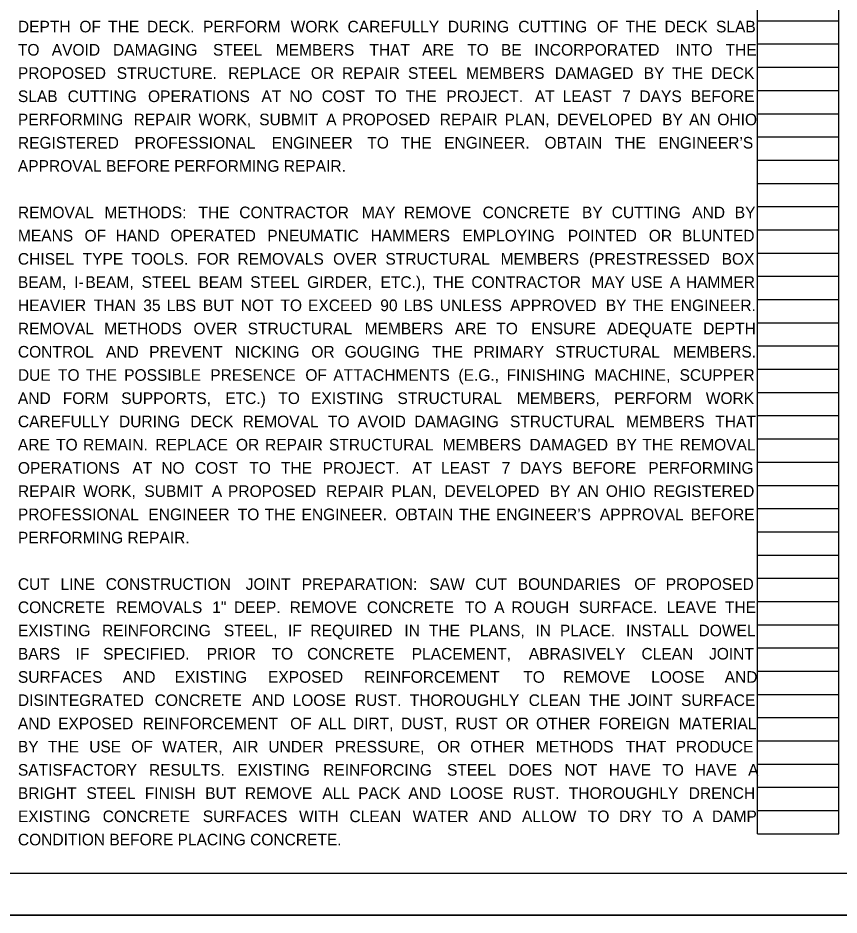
# Model space of a CAD drawing. Extents: x 0 to 34, y 0 to 22.
# Drawn here: x 12.29 to 22.19, y 0 to 10.81 of the extents above; entities that cross this region are included whole.
import ezdxf

# ---------------------------------------------------------------- set-up
doc = ezdxf.new("R2010")
doc.units = 0
for name, color, linetype in [('SC_Scratch1', 7, 'Continuous'), ('SH_Border', 7, 'Continuous'), ('SH_Cut_Line', 7, 'Continuous'), ('SH_Text', 7, 'Continuous')]:
    doc.layers.add(name, color=color, linetype=linetype)

msp = doc.modelspace()

# ---------------------------------------------------------------- linework, layer by layer
at = {"layer": 'SC_Scratch1'}
for p, q in [((21.207, 0.98), (21.207, 21.14)), ((22.187, 0.98), (22.187, 21.14)), ((21.207, 10.78), (22.187, 10.78)), ((21.207, 10.5), (22.187, 10.5)), ((21.207, 10.22), (22.187, 10.22)), ((21.207, 9.94), (22.187, 9.94)), ((21.207, 9.66), (22.187, 9.66)), ((21.207, 9.38), (22.187, 9.38)), ((21.207, 9.1), (22.187, 9.1)), ((21.207, 8.82), (22.187, 8.82)), ((21.207, 8.54), (22.187, 8.54)), ((21.207, 8.26), (22.187, 8.26)), ((21.207, 7.98), (22.187, 7.98)), ((21.207, 7.7), (22.187, 7.7)), ((21.207, 7.42), (22.187, 7.42)), ((21.207, 7.14), (22.187, 7.14)), ((21.207, 6.86), (22.187, 6.86)), ((21.207, 6.58), (22.187, 6.58)), ((21.207, 6.3), (22.187, 6.3)), ((21.207, 6.02), (22.187, 6.02)), ((21.207, 5.74), (22.187, 5.74)), ((21.207, 5.46), (22.187, 5.46)), ((21.207, 5.18), (22.187, 5.18)), ((21.207, 4.9), (22.187, 4.9)), ((21.207, 4.62), (22.187, 4.62)), ((21.207, 4.34), (22.187, 4.34)), ((21.207, 4.06), (22.187, 4.06)), ((21.207, 3.78), (22.187, 3.78)), ((21.207, 3.5), (22.187, 3.5)), ((21.207, 3.22), (22.187, 3.22)), ((21.207, 2.94), (22.187, 2.94)), ((21.207, 2.66), (22.187, 2.66)), ((21.207, 2.38), (22.187, 2.38)), ((21.207, 2.1), (22.187, 2.1)), ((21.207, 1.82), (22.187, 1.82)), ((21.207, 1.54), (22.187, 1.54)), ((21.207, 1.26), (22.187, 1.26)), ((21.207, 0.98), (22.187, 0.98))]:
    msp.add_line(p, q, dxfattribs=at)
msp.add_lwpolyline([(0, 22), (34, 22), (34, 0), (0, 0)], close=True, dxfattribs=at)
at = {"layer": 'SH_Border'}
msp.add_lwpolyline([(1.5, 21.5), (33.5, 21.5), (33.5, 0.5), (1.5, 0.5)], close=True, dxfattribs=at)
at = {"layer": 'SH_Cut_Line'}
msp.add_lwpolyline([(0, 0), (34, 0), (34, 22), (0, 22)], close=True, dxfattribs=at)

# ---------------------------------------------------------------- texts
at = {"layer": 'SH_Text'}
for s, p in [('DEPTH ', (12.293, 10.64)), ('OF ', (13.034, 10.64)), ('THE ', (13.38, 10.64)), ('DECK. ', (13.849, 10.64)), ('PERFORM ', (14.524, 10.64)), ('WORK ', (15.58, 10.64)), ('CAREFULLY ', (16.266, 10.64)), ('DURING ', (17.474, 10.64)), ('CUTTING ', (18.323, 10.64)), ('OF ', (19.27, 10.64)), ('THE ', (19.616, 10.64)), ('DECK ', (20.085, 10.64)), ('SLAB ', (20.706, 10.64)), ('TO ', (12.293, 10.36)), ('AVOID ', (12.701, 10.36)), ('DAMAGING ', (13.439, 10.36)), ('STEEL ', (14.644, 10.36)), ('MEMBERS ', (15.4, 10.36)), ('THAT ', (16.529, 10.36)), ('ARE ', (17.165, 10.36)), ('TO ', (17.707, 10.36)), ('BE ', (18.115, 10.36)), ('INCORPORATED ', (18.516, 10.36)), ('INTO ', (20.217, 10.36)), ('THE ', (20.821, 10.36)), ('PROPOSED ', (12.293, 10.08)), ('STRUCTURE. ', (13.484, 10.08)), ('REPLACE ', (14.827, 10.08)), ('OR ', (15.823, 10.08)), ('REPAIR ', (16.198, 10.08)), ('STEEL ', (16.994, 10.08)), ('MEMBERS ', (17.693, 10.08)), ('DAMAGED ', (18.764, 10.08)), ('BY ', (19.835, 10.08)), ('THE ', (20.175, 10.08)), ('DECK ', (20.648, 10.08)), ('SLAB ', (12.293, 9.8)), ('CUTTING ', (12.893, 9.8)), ('OPERATIONS ', (13.861, 9.8)), ('AT ', (15.228, 9.8)), ('NO ', (15.563, 9.8)), ('COST ', (15.955, 9.8)), ('TO ', (16.598, 9.8)), ('THE ', (16.965, 9.8)), ('PROJECT. ', (17.456, 9.8)), ('AT ', (18.522, 9.8)), ('LEAST ', (18.857, 9.8)), ('7 ', (19.575, 9.8)), ('DAYS ', (19.783, 9.8)), ('BEFORE ', (20.401, 9.8)), ('PERFORMING ', (12.293, 9.52)), ('REPAIR ', (13.687, 9.52)), ('WORK, ', (14.47, 9.52)), ('SUBMIT ', (15.201, 9.52)), ('A ', (16.008, 9.52)), ('PROPOSED ', (16.199, 9.52)), ('REPAIR ', (17.377, 9.52)), ('PLAN, ', (18.159, 9.52)), ('DEVELOPED ', (18.792, 9.52)), ('BY ', (20.057, 9.52)), ('AN ', (20.382, 9.52)), ('OHIO ', (20.722, 9.52)), ('REGISTERED ', (12.293, 9.24)), ('PROFESSIONAL ', (13.698, 9.24)), ('ENGINEER ', (15.35, 9.24)), ('TO ', (16.504, 9.24)), ('THE ', (16.906, 9.24)), ('ENGINEER. ', (17.43, 9.24)), ('OBTAIN ', (18.639, 9.24)), ('THE ', (19.486, 9.24)), ('ENGINEER’S ', (20.01, 9.24)), ('APPROVAL BEFORE PERFORMING REPAIR. ', (12.293, 8.96)), ('REMOVAL ', (12.293, 8.4)), ('METHODS: ', (13.336, 8.4)), ('THE ', (14.469, 8.4)), ('CONTRACTOR ', (14.961, 8.4)), ('MAY ', (16.438, 8.4)), ('REMOVE ', (16.944, 8.4)), ('CONCRETE ', (17.893, 8.4)), ('BY ', (19.091, 8.4)), ('CUTTING ', (19.449, 8.4)), ('AND ', (20.419, 8.4)), ('BY ', (20.932, 8.4)), ('MEANS ', (12.293, 8.12)), ('OF ', (13.096, 8.12)), ('HAND ', (13.47, 8.12)), ('OPERATED ', (14.131, 8.12)), ('PNEUMATIC ', (15.299, 8.12)), ('HAMMERS ', (16.543, 8.12)), ('EMPLOYING ', (17.65, 8.12)), ('POINTED ', (18.92, 8.12)), ('OR ', (19.896, 8.12)), ('BLUNTED ', (20.296, 8.12)), ('CHISEL ', (12.293, 7.84)), ('TYPE ', (13.073, 7.84)), ('TOOLS. ', (13.66, 7.84)), ('FOR ', (14.45, 7.84)), ('REMOVALS ', (14.939, 7.84)), ('OVER ', (16.092, 7.84)), ('STRUCTURAL ', (16.722, 7.84)), ('MEMBERS ', (18.11, 7.84)), ('(PRESTRESSED ', (19.175, 7.84)), ('BOX ', (20.774, 7.84)), ('BEAM, ', (12.293, 7.56)), ('I-', (12.971, 7.56)), ('BEAM, ', (13.106, 7.56)), ('STEEL ', (13.784, 7.56)), ('BEAM ', (14.469, 7.56)), ('STEEL ', (15.093, 7.56)), ('GIRDER, ', (15.778, 7.56)), ('ETC.), ', (16.663, 7.56)), ('THE ', (17.297, 7.56)), ('CONTRACTOR ', (17.758, 7.56)), ('MAY ', (19.204, 7.56)), ('USE ', (19.679, 7.56)), ('A ', (20.15, 7.56)), ('HAMMER ', (20.343, 7.56)), ('HEAVIER ', (12.293, 7.28)), ('THAN ', (13.207, 7.28)), ('35 ', (13.804, 7.28)), ('LBS ', (14.087, 7.28)), ('BUT ', (14.522, 7.28)), ('NOT ', (14.979, 7.28)), ('TO ', (15.457, 7.28)), ('EXCEED ', (15.79, 7.28)), ('90 ', (16.66, 7.28)), ('LBS ', (16.943, 7.28)), ('UNLESS ', (17.377, 7.28)), ('APPROVED ', (18.225, 7.28)), ('BY ', (19.378, 7.28)), ('THE ', (19.701, 7.28)), ('ENGINEER. ', (20.157, 7.28)), ('REMOVAL ', (12.293, 7)), ('METHODS ', (13.333, 7)), ('OVER ', (14.409, 7)), ('STRUCTURAL ', (15.062, 7)), ('MEMBERS ', (16.471, 7)), ('ARE ', (17.558, 7)), ('TO  ', (18.058, 7)), ('ENSURE ', (18.479, 7)), ('ADEQUATE ', (19.392, 7)), ('DEPTH ', (20.551, 7)), ('CONTROL ', (12.293, 6.72)), ('AND ', (13.354, 6.72)), ('PREVENT ', (13.875, 6.72)), ('NICKING ', (14.906, 6.72)), ('OR ', (15.829, 6.72)), ('GOUGING ', (16.23, 6.72)), ('THE ', (17.283, 6.72)), ('PRIMARY ', (17.782, 6.72)), ('STRUCTURAL ', (18.77, 6.72)), ('MEMBERS. ', (20.19, 6.72)), ('DUE ', (12.293, 6.44)), ('TO ', (12.776, 6.44)), ('THE ', (13.113, 6.44)), ('POSSIBLE ', (13.574, 6.44)), ('PRESENCE ', (14.611, 6.44)), ('OF ', (15.757, 6.44)), ('ATTACHMENTS ', (16.094, 6.44)), ('(E.G., ', (17.602, 6.44)), ('FINISHING ', (18.182, 6.44)), ('MACHINE, ', (19.241, 6.44)), ('SCUPPER ', (20.267, 6.44)), ('AND ', (12.293, 6.16)), ('FORM ', (12.834, 6.16)), ('SUPPORTS, ', (13.538, 6.16)), ('ETC.) ', (14.792, 6.16)), ('TO ', (15.431, 6.16)), ('EXISTING ', (15.826, 6.16)), ('STRUCTURAL ', (16.867, 6.16)), ('MEMBERS, ', (18.306, 6.16)), ('PERFORM ', (19.478, 6.16)), ('WORK ', (20.583, 6.16)), ('CAREFULLY ', (12.293, 5.88)), ('DURING ', (13.511, 5.88)), ('DECK ', (14.37, 5.88)), ('REMOVAL ', (15.001, 5.88)), ('TO ', (16.03, 5.88)), ('AVOID ', (16.386, 5.88)), ('DAMAGING ', (17.071, 5.88)), ('STRUCTURAL ', (18.223, 5.88)), ('MEMBERS ', (19.622, 5.88)), ('THAT ', (20.698, 5.88)), ('ARE ', (12.293, 5.6)), ('TO ', (12.753, 5.6)), ('REMAIN. ', (13.078, 5.6)), ('REPLACE ', (13.95, 5.6)), ('OR ', (14.921, 5.6)), ('REPAIR ', (15.271, 5.6)), ('STRUCTURAL ', (16.042, 5.6)), ('MEMBERS ', (17.411, 5.6)), ('DAMAGED ', (18.458, 5.6)), ('BY ', (19.504, 5.6)), ('THE ', (19.818, 5.6)), ('REMOVAL ', (20.267, 5.6)), ('OPERATIONS ', (12.293, 5.32)), ('AT ', (13.673, 5.32)), ('NO ', (14.021, 5.32)), ('COST ', (14.426, 5.32)), ('TO ', (15.082, 5.32)), ('THE ', (15.462, 5.32)), ('PROJECT. ', (15.965, 5.32)), ('AT ', (17.044, 5.32)), ('LEAST ', (17.391, 5.32)), ('7 ', (18.123, 5.32)), ('DAYS ', (18.344, 5.32)), ('BEFORE ', (18.974, 5.32)), ('PERFORMING ', (19.89, 5.32)), ('REPAIR ', (12.293, 5.04)), ('WORK, ', (13.08, 5.04)), ('SUBMIT ', (13.817, 5.04)), ('A ', (14.629, 5.04)), ('PROPOSED ', (14.825, 5.04)), ('REPAIR ', (16.007, 5.04)), ('PLAN, ', (16.795, 5.04)), ('DEVELOPED ', (17.433, 5.04)), ('BY ', (18.702, 5.04)), ('AN ', (19.033, 5.04)), ('OHIO ', (19.378, 5.04)), ('REGISTERED ', (19.951, 5.04)), ('PROFESSIONAL ', (12.293, 4.76)), ('ENGINEER ', (13.866, 4.76)), ('TO ', (14.942, 4.76)), ('THE ', (15.265, 4.76)), ('ENGINEER. ', (15.711, 4.76)), ('OBTAIN ', (16.841, 4.76)), ('THE ', (17.61, 4.76)), ('ENGINEER’S ', (18.055, 4.76)), ('APPROVAL ', (19.306, 4.76)), ('BEFORE ', (20.401, 4.76)), ('PERFORMING REPAIR. ', (12.293, 4.48)), ('CUT ', (12.293, 3.92)), ('LINE ', (12.806, 3.92)), ('CONSTRUCTION ', (13.351, 3.92)), ('JOINT ', (15.038, 3.92)), ('PREPARATION: ', (15.713, 3.92)), ('SAW ', (17.252, 3.92)), ('CUT ', (17.804, 3.92)), ('BOUNDARIES ', (18.317, 3.92)), ('OF ', (19.721, 3.92)), ('PROPOSED ', (20.1, 3.92)), ('CONCRETE ', (12.293, 3.64)), ('REMOVALS ', (13.475, 3.64)), ('1" ', (14.635, 3.64)), ('DEEP. ', (14.897, 3.64)), ('REMOVE ', (15.568, 3.64)), ('CONCRETE ', (16.499, 3.64)), ('TO ', (17.681, 3.64)), ('A ', (18.033, 3.64)), ('ROUGH ', (18.24, 3.64)), ('SURFACE. ', (19.052, 3.64)), ('LEAVE ', (20.11, 3.64)), ('THE ', (20.814, 3.64)), ('EXISTING ', (12.293, 3.36)), ('REINFORCING ', (13.306, 3.36)), ('STEEL, ', (14.775, 3.36)), ('IF ', (15.548, 3.36)), ('REQUIRED ', (15.818, 3.36)), ('IN ', (16.95, 3.36)), ('THE ', (17.245, 3.36)), ('PLANS, ', (17.735, 3.36)), ('IN ', (18.53, 3.36)), ('PLACE. ', (18.825, 3.36)), ('INSTALL ', (19.621, 3.36)), ('DOWEL ', (20.496, 3.36)), ('BARS ', (12.293, 3.08)), ('IF ', (12.988, 3.08)), ('SPECIFIED. ', (13.32, 3.08)), ('PRIOR ', (14.568, 3.08)), ('TO ', (15.349, 3.08)), ('CONCRETE ', (15.779, 3.08)), ('PLACEMENT, ', (17.039, 3.08)), ('ABRASIVELY ', (18.45, 3.08)), ('CLEAN ', (19.808, 3.08)), ('JOINT ', (20.622, 3.08)), ('SURFACES ', (12.293, 2.8)), ('AND ', (13.556, 2.8)), ('EXISTING ', (14.182, 2.8)), ('EXPOSED ', (15.307, 2.8)), ('REINFORCEMENT ', (16.465, 2.8)), ('TO ', (18.383, 2.8)), ('REMOVE ', (18.864, 2.8)), ('LOOSE ', (19.924, 2.8)), ('AND ', (20.81, 2.8)), ('DISINTEGRATED ', (12.293, 2.52)), ('CONCRETE ', (13.941, 2.52)), ('AND ', (15.115, 2.52)), ('LOOSE ', (15.603, 2.52)), ('RUST. ', (16.353, 2.52)), ('THOROUGHLY ', (17.015, 2.52)), ('CLEAN ', (18.449, 2.52)), ('THE ', (19.177, 2.52)), ('JOINT ', (19.644, 2.52)), ('SURFACE ', (20.285, 2.52)), ('AND ', (12.293, 2.24)), ('EXPOSED ', (12.778, 2.24)), ('REINFORCEMENT ', (13.796, 2.24)), ('OF ', (15.574, 2.24)), ('ALL ', (15.914, 2.24)), ('DIRT, ', (16.33, 2.24)), ('DUST, ', (16.909, 2.24)), ('RUST ', (17.567, 2.24)), ('OR ', (18.172, 2.24)), ('OTHER ', (18.537, 2.24)), ('FOREIGN ', (19.293, 2.24)), ('MATERIAL ', (20.256, 2.24)), ('BY ', (12.293, 1.96)), ('THE ', (12.656, 1.96)), ('USE ', (13.152, 1.96)), ('OF ', (13.659, 1.96)), ('WATER, ', (14.032, 1.96)), ('AIR ', (14.88, 1.96)), ('UNDER ', (15.311, 1.96)), ('PRESSURE, ', (16.111, 1.96)), ('OR ', (17.347, 1.96)), ('OTHER ', (17.745, 1.96)), ('METHODS ', (18.535, 1.96)), ('THAT ', (19.618, 1.96)), ('PRODUCE ', (20.219, 1.96)), ('SATISFACTORY ', (12.293, 1.68)), ('RESULTS. ', (13.872, 1.68)), ('EXISTING ', (14.937, 1.68)), ('REINFORCING ', (15.972, 1.68)), ('STEEL ', (17.464, 1.68)), ('DOES ', (18.202, 1.68)), ('NOT ', (18.879, 1.68)), ('HAVE ', (19.414, 1.68)), ('TO ', (20.058, 1.68)), ('HAVE ', (20.449, 1.68)), ('A ', (21.093, 1.68)), ('BRIGHT ', (12.293, 1.4)), ('STEEL ', (13.119, 1.4)), ('FINISH ', (13.822, 1.4)), ('BUT ', (14.55, 1.4)), ('REMOVE ', (15.028, 1.4)), ('ALL ', (15.962, 1.4)), ('PACK ', (16.393, 1.4)), ('AND ', (16.998, 1.4)), ('LOOSE ', (17.498, 1.4)), ('RUST. ', (18.258, 1.4)), ('THOROUGHLY ', (18.932, 1.4)), ('DRENCH ', (20.377, 1.4)), ('EXISTING ', (12.293, 1.12)), ('CONCRETE ', (13.315, 1.12)), ('SURFACES ', (14.521, 1.12)), ('WITH ', (15.681, 1.12)), ('CLEAN ', (16.289, 1.12)), ('WATER ', (17.05, 1.12)), ('AND ', (17.846, 1.12)), ('ALLOW ', (18.368, 1.12)), ('TO ', (19.161, 1.12)), ('DRY ', (19.538, 1.12)), ('TO ', (20.049, 1.12)), ('A ', (20.425, 1.12)), ('DAMP ', (20.657, 1.12)), ('CONDITION BEFORE PLACING CONCRETE. ', (12.293, 0.84))]:
    msp.add_text(s, height=0.14, dxfattribs=at).set_placement(p)

doc.saveas('drawing.dxf')
